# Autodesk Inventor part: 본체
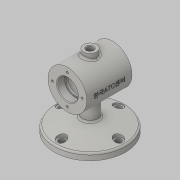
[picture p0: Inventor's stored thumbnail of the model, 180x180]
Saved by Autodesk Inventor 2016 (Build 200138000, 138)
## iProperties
Created: 2018-12
Part Number: 본체
Material: Generic
Document SubType Name: Modeling
Designer: Administrator
Density: 1 g/cm^3
Appearance: Default
Mass: 245.081 g
Surface Area: 551.221 cm^2
Volume: 245.081 cm^3
Author: Administrator
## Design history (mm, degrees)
sketch "스케치1"
  geometry: C1 r 55 at (0, 0); 1 further point
  constraints: 1 centre point, 1 coincident
  dimensions: "d0" = 110 diameter of C1
extrude "돌출1" new body sketch "스케치1" distance "d1" = 10; taper "d2" = 0 deg
sketch "스케치3"
  geometry: C1 r 12 at (0, 0); 1 further point
  constraints: 1 centre point, 1 coincident
  dimensions: "d3" = 24 diameter of C1
extrude "돌출2" join sketch "스케치3" distance "d4" = 64; taper "d5" = 0 deg
sketch "스케치4"
  geometry: L1 (10, -55)-(10, 55) reference; L2 (10, 55)-(21.522, 12); L3 (10, 12)-(74, 12) reference; L4 (21.522, 12)-(21.522, 0); L5 (10, -12)-(74, -12) reference; L6 (21.522, 0)-(10, 0); L7 (0, 55)-(10, 55) reference; 1 further point
  constraints: 6 end point, 1 midpoint, 1 perpendicular, 1 point on line
  dimensions: "d6" = 75 deg angle of L7 L2; "d7" = 11.52182 distance between parallel lines of L4 L1 (derived); "d8" = 24 diameter of L2.end L6
revolve "회전1" sketch "스케치4" stored, may be unused: angle "d9" = 90 deg
sketch "스케치5"
  geometry: L1 (12, 74)-(-12, 74) reference; C1 r 30 at (0, 74); 1 further point
  constraints: 1 centre point, 1 midpoint
  dimensions: "d10" = 60 diameter of C1
extrude "돌출3" join sketch "스케치5" stored distance "d11" = 70; taper "d12" = 0 deg
node "작업 평면1"
sketch "스케치6"
  geometry: C1 r 10 at (0, 0); 1 further point
  constraints: 1 centre point, 1 coincident
  dimensions: "d14" = 20 diameter of C1
extrude "돌출4" join sketch "스케치6" stored distance "d15" = 70; taper "d16" = 0 deg
hole "구멍1" diameter "d19" = 32; stored, may be unused: countersink angle "d23" = 90 deg, drill point angle "d25" = 0 deg; dims "d17" = 10, "d18" = 10, "d20" = 6, "d21" = 4, "d22" = 2, "d24" = 12
hole "구멍2" diameter "d28" = 28; stored, may be unused: countersink angle "d32" = 90 deg, drill point angle "d34" = 0 deg; dims "d26" = 10, "d27" = 10, "d29" = 6, "d30" = 4, "d31" = 2, "d33" = 3
hole "구멍3" diameter "d37" = 50; stored, may be unused: countersink angle "d41" = 90 deg, drill point angle "d43" = 0 deg; dims "d35" = 10, "d36" = 10, "d38" = 6, "d39" = 4, "d40" = 2, "d42" = 40
hole "구멍4" diameter "d46" = 28; stored, may be unused: countersink angle "d50" = 90 deg, drill point angle "d52" = 0 deg; dims "d44" = 10, "d45" = 10, "d47" = 6, "d48" = 4, "d49" = 2, "d51" = 3
hole "구멍5" diameter "d55" = 32; stored, may be unused: countersink angle "d59" = 90 deg, drill point angle "d61" = 0 deg; dims "d53" = 10, "d54" = 10, "d56" = 6, "d57" = 4, "d58" = 2, "d60" = 12
hole "구멍6" diameter "d64" = 10; stored, may be unused: countersink angle "d68" = 90 deg, drill point angle "d70" = 0 deg; dims "d62" = 10, "d63" = 10, "d65" = 6, "d66" = 4, "d67" = 2, "d69" = 20
sketch "스케치7" dims "d71" = 46
  geometry: 3 further points
  constraints: 1 vertical alignment, 2 other
hole "구멍7" sketch "스케치7" at (0, 23) diameter "d72" = 3.242; stored, may be unused: countersink angle "d76" = 90 deg, drill point angle "d78" = 118 deg; dims "d73" = 8, "d74" = 4, "d75" = 2, "d77" = 10
node "작업 평면2"
sketch "스케치8" dims "d83" = 88
  geometry: C1 r 4.5 at (44, 0); 2 further points
  constraints: 1 centre point, 1 coincident, 1 horizontal alignment, 2 other
  dimensions: "d84" = 9 diameter of C1
extrude "돌출5" cut sketch "스케치8" stored distance "d85" = 70; taper "d86" = 0 deg
sketch "스케치9"
  geometry: C1 r 4.5 at (44, 0) reference; C2 r 7 at (44, 0); 1 further point
  constraints: 1 centre point, 1 coincident
  dimensions: "d87" = 14 diameter of C2
extrude "돌출6" cut sketch "스케치9" distance "d88" = 70; taper "d89" = 0 deg
fillet "모깎기1" dims "d93" = 3
fillet "모깎기2" dims "d94" = 3
chamfer "모따기1" distance "d95" = 1; stored, may be unused: second distance "d96" = 2, angle "d97" = 45 deg
fillet "모깎기3" dims "d98" = 0.3
node "작업 평면3"
sketch "스케치10"
  geometry: L1 (30, -35)-(30, 35) reference; L2 (30, 35)-(-30, 35) reference; 2 further points
  constraints: 1 other
  dimensions: "d99" = 30 distance from line of point (0, 0) L1; "d100" = 35 distance from line of L2 point (0, 0)
feature "엠보싱1" sketch "스케치10" dims "d2" = 0, "d9" = 90 deg, "d101" = 0.5, "d102" = 0
node "솔리드1"
pattern_circular "원형 패턴1" dims angle "d80" = 360 deg
mirror "대칭1"
pattern_circular "원형 패턴2" dims angle "d91" = 360 deg
other parameters: "d13" = 112
